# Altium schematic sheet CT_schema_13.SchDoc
size 501 x 385 mm
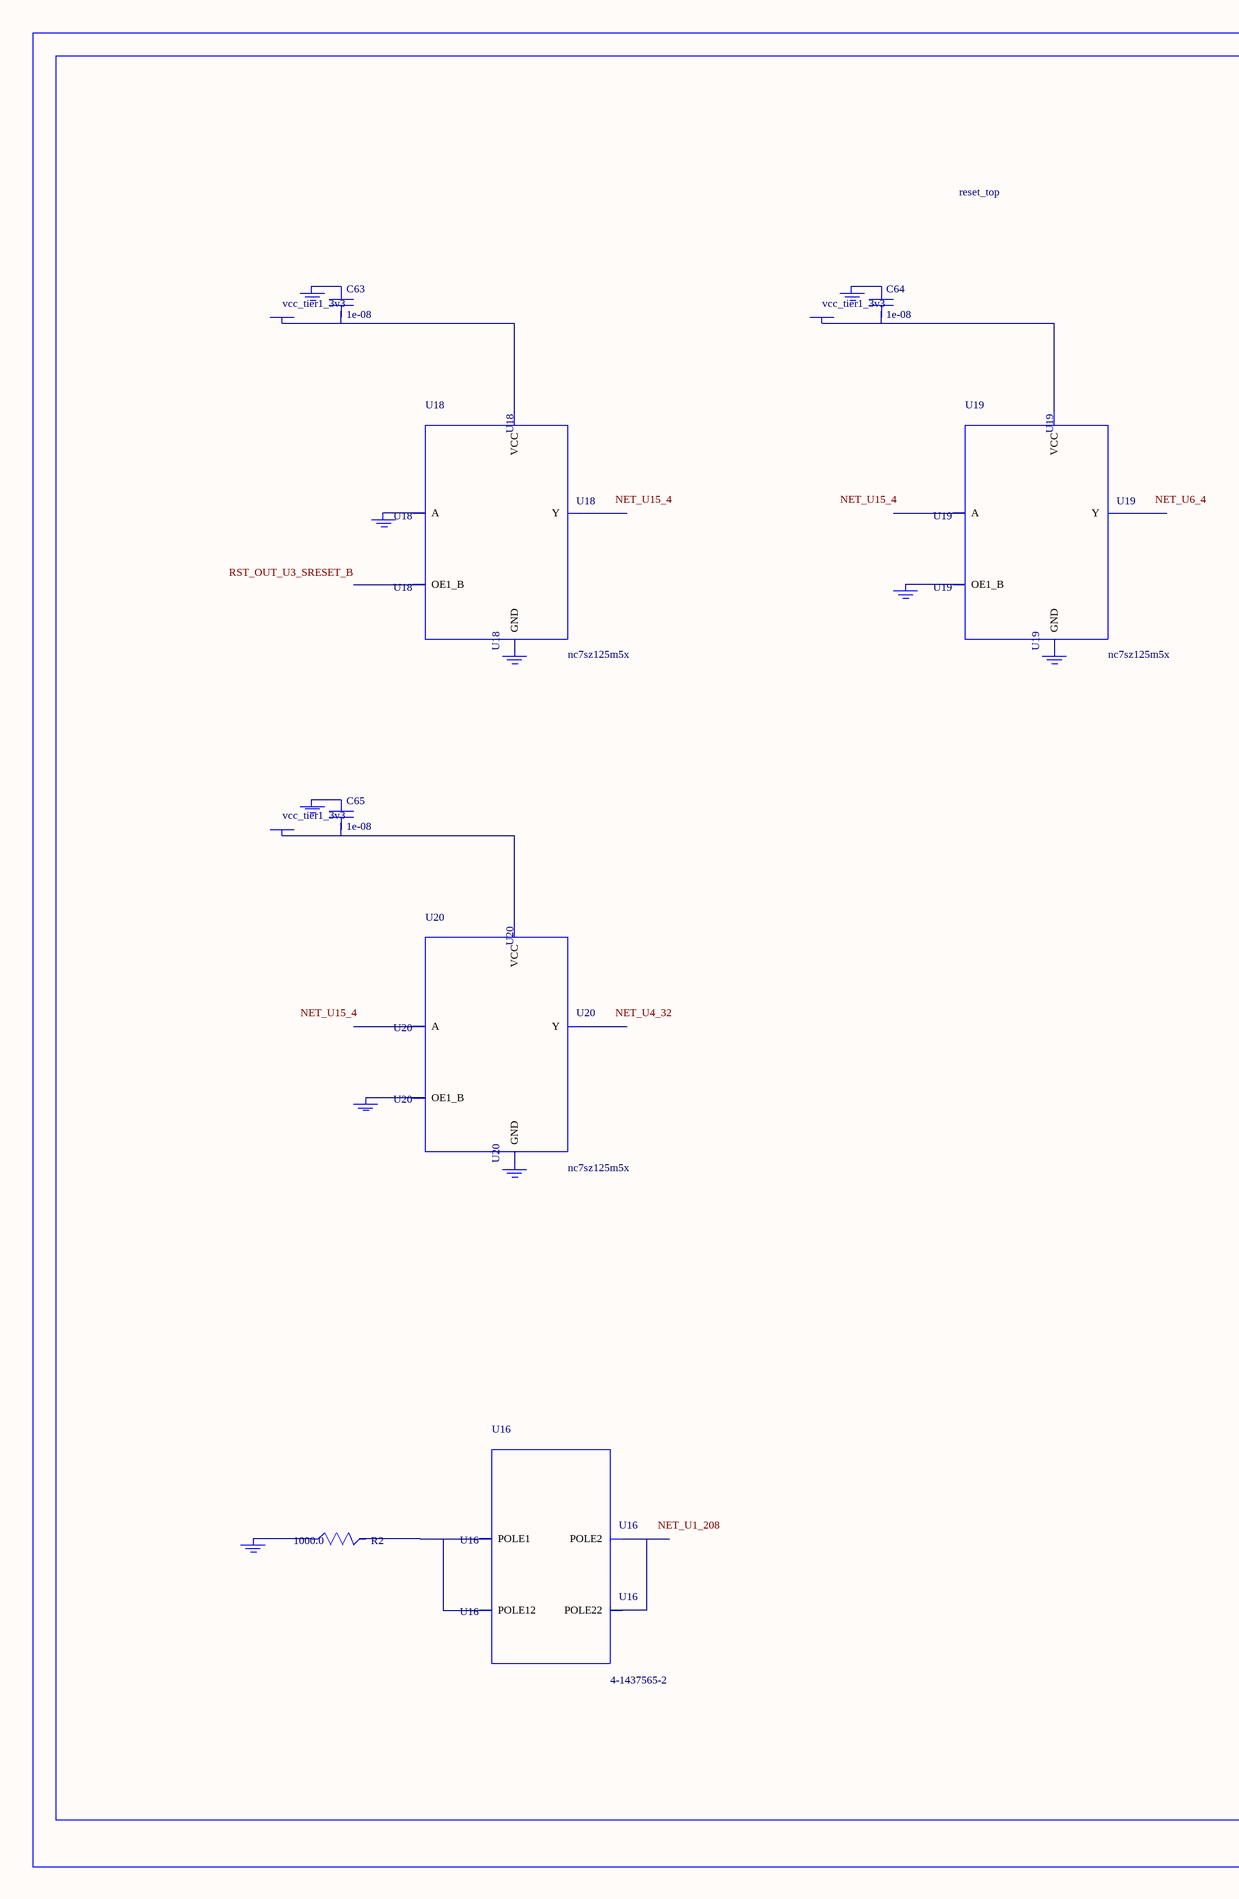
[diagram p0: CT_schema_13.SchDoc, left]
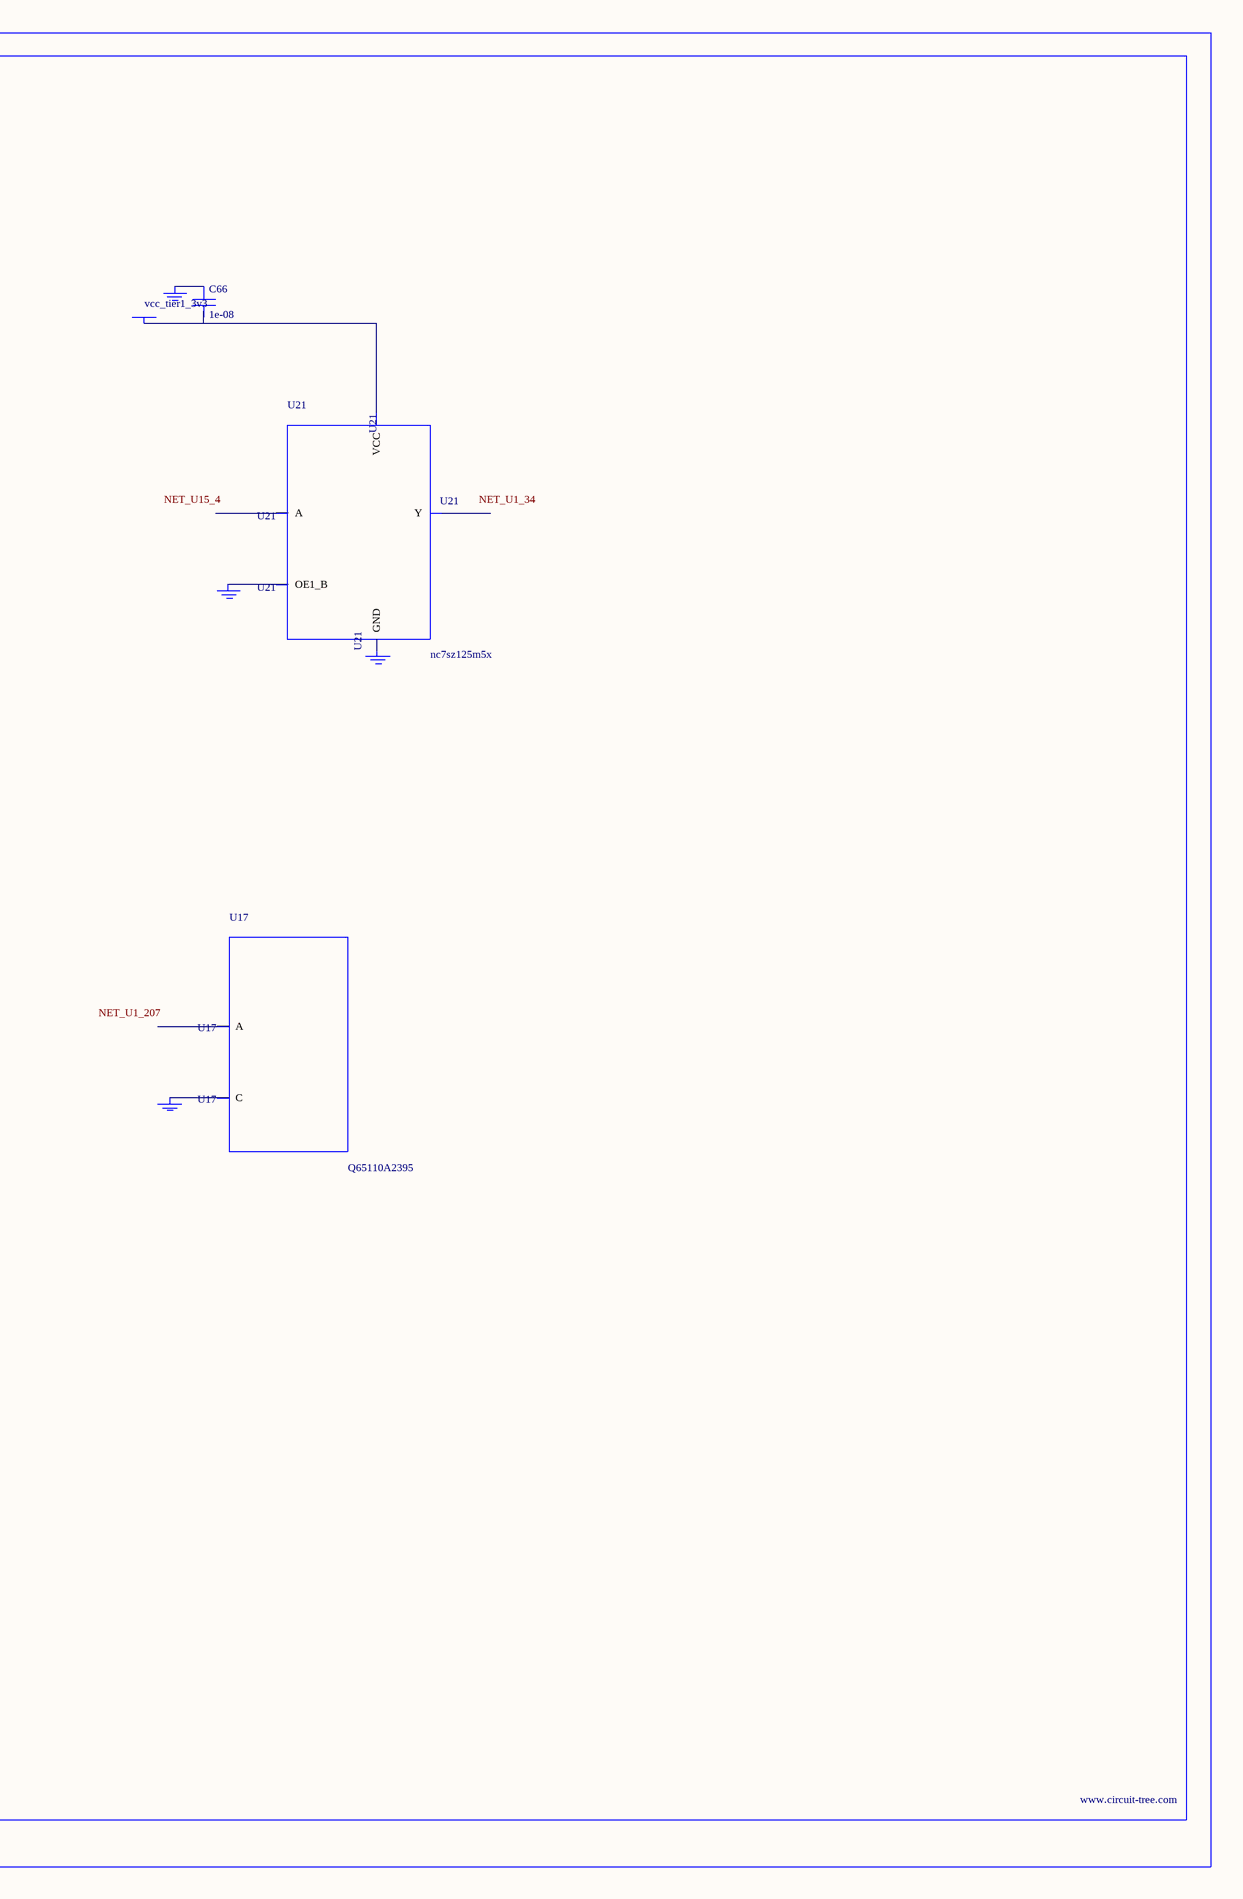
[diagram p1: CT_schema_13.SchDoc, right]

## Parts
BORDER12  (no value)
C63  1e-08  [C0402]
C64  1e-08  [C0402]
C65  1e-08  [C0402]
C66  1e-08  [C0402]
GND_INSTANCE_12_0  (no value)
GND_INSTANCE_12_1  (no value)
GND_INSTANCE_12_2  (no value)
GND_INSTANCE_12_3  (no value)
GND_INSTANCE_12_4  (no value)
GND_INSTANCE_12_5  (no value)
GND_INSTANCE_12_6  (no value)
GND_INSTANCE_12_7  (no value)
GND_INSTANCE_12_8  (no value)
GND_INSTANCE_12_9  (no value)
GND_INSTANCE_12_10  (no value)
GND_INSTANCE_12_11  (no value)
GND_INSTANCE_12_12  (no value)
GND_INSTANCE_12_13  (no value)
POWER_INSTANCE_12_0  vcc_tier1_3v3
POWER_INSTANCE_12_1  vcc_tier1_3v3
POWER_INSTANCE_12_2  vcc_tier1_3v3
POWER_INSTANCE_12_3  vcc_tier1_3v3
R2  1000.0  [R0603]
U16  4-1437565-2  [SW_4-1437565-2]
U17  Q65110A2395  [LGM67K-G1J2-24-Z]
U18  nc7sz125m5x  [NC7SZ125M5X]
U19  nc7sz125m5x  [NC7SZ125M5X]
U20  nc7sz125m5x  [NC7SZ125M5X]
U21  nc7sz125m5x  [NC7SZ125M5X]

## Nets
NetC63_1: C63.1 GND_INSTANCE_12_2.0(GND)
NetC63_2: C63.2 POWER_INSTANCE_12_0.0(PWR) U18.5(VCC)
NetC64_1: C64.1 GND_INSTANCE_12_5.0(GND)
NetC64_2: C64.2 POWER_INSTANCE_12_1.0(PWR) U19.5(VCC)
NetC65_1: C65.1 GND_INSTANCE_12_8.0(GND)
NetC65_2: C65.2 POWER_INSTANCE_12_2.0(PWR) U20.5(VCC)
NetC66_1: C66.1 GND_INSTANCE_12_11.0(GND)
NetC66_2: C66.2 POWER_INSTANCE_12_3.0(PWR) U21.5(VCC)
NetGND_INSTANCE_12_0_0: GND_INSTANCE_12_0.0(GND) R2.1
NetGND_INSTANCE_12_1_0: GND_INSTANCE_12_1.0(GND) U17.C
NetGND_INSTANCE_12_3_0: GND_INSTANCE_12_3.0(GND) U18.2(A)
NetGND_INSTANCE_12_4_0: GND_INSTANCE_12_4.0(GND) U18.3(GND)
NetGND_INSTANCE_12_6_0: GND_INSTANCE_12_6.0(GND) U19.1(OE1_B)
NetGND_INSTANCE_12_7_0: GND_INSTANCE_12_7.0(GND) U19.3(GND)
NetGND_INSTANCE_12_9_0: GND_INSTANCE_12_9.0(GND) U20.1(OE1_B)
NetGND_INSTANCE_12_10_0: GND_INSTANCE_12_10.0(GND) U20.3(GND)
NetGND_INSTANCE_12_12_0: GND_INSTANCE_12_12.0(GND) U21.1(OE1_B)
NetGND_INSTANCE_12_13_0: GND_INSTANCE_12_13.0(GND) U21.3(GND)
NetR2_2: R2.2 U16.1(POLE1) U16.2(POLE12)
NetU16_3: U16.3(POLE2) U16.4(POLE22)

Not connected (* = marked no-connect by the designer): U17 A; U18 1(OE1_B) 4(Y); U19 2(A) 4(Y); U20 2(A) 4(Y); U21 2(A) 4(Y)

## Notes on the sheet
- Labels drawn without touching a wire or pin: NET_U1_34, NET_U1_207, NET_U1_208, NET_U4_32, NET_U6_4, NET_U15_4, RST_OUT_U3_SRESET_B

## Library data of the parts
BORDER12 = BORDER_PAGE12
C63-C66 = C0402C103K3RAC
GND_INSTANCE_12_0-GND_INSTANCE_12_13 = GND
POWER_INSTANCE_12_0-POWER_INSTANCE_12_3 = PWR
R2 = RC0603JR-071KL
